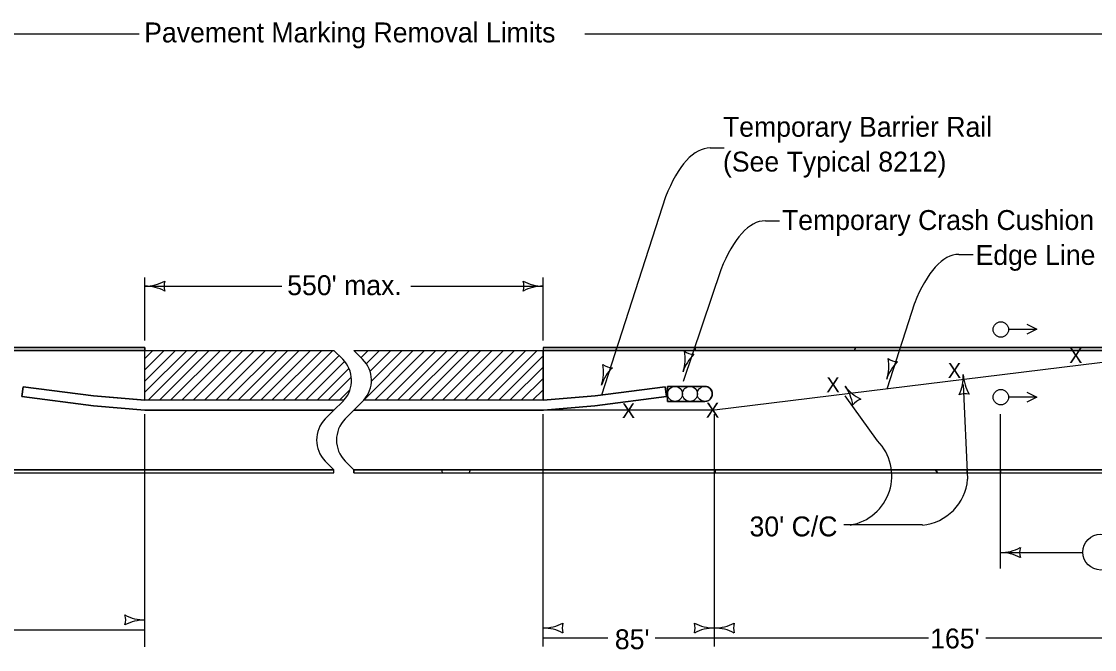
# Model space of a CAD drawing. Extents: x 10133 to 81668, y 4692 to 11018.
# Drawn here: x 22169 to 23247, y 6624 to 7255 of the extents above; entities that cross this region are included whole.
import ezdxf

# ---------------------------------------------------------------- set-up
doc = ezdxf.new("R2010")
doc.units = 0
for name, color, linetype in [('dsnCellElements', 7, 'Continuous'), ('dsnStdShading', 7, 'Continuous'), ('dsnTextTabulation', 7, 'Continuous'), ('Level 8', 7, 'Continuous')]:
    doc.layers.add(name, color=color, linetype=linetype)

msp = doc.modelspace()

# ---------------------------------------------------------------- linework, layer by layer
at = {"layer": 'dsnCellElements'}
for p, q in [((21627.5, 7243), (22286.9, 7243)), ((22734.5, 7243), (23352.5, 7243)), ((22860.4, 7128.3), (22874.6, 7128.3)), ((22815.7, 7079.2), (22751.3, 6880)), ((22915.9, 7055.2), (22930.1, 7055.2)), ((23110.4, 7021.4), (23124.6, 7021.4)), ((22292.5, 6934.8), (22292.5, 6998.1)), ((22692.5, 6934.8), (22692.5, 6998.1)), ((22871.1, 7006), (22833.2, 6893.5)), ((22292.5, 6989.5), (22430, 6989.5)), ((22559.8, 6989.5), (22692.5, 6989.5)), ((23065.7, 6972.2), (23037.8, 6886.1)), ((23160.3, 6946.3), (23188.2, 6946.3)), ((22292.5, 6924.8), (20982.5, 6924.8)), ((22292.5, 6916.7), (22300.6, 6924.8)), ((22292.5, 6905.4), (22311.9, 6924.8)), ((22292.5, 6894.1), (22323.2, 6924.8)), ((22292.5, 6874.8), (22292.5, 6924.8)), ((22292.5, 6882.8), (22334.5, 6924.8)), ((22292.5, 6874.8), (22292.5, 6924.8)), ((22295.8, 6874.8), (22345.8, 6924.8)), ((22307.1, 6874.8), (22357.1, 6924.8)), ((22318.4, 6874.8), (22368.4, 6924.8)), ((22329.7, 6874.8), (22379.7, 6924.8)), ((22341, 6874.8), (22391, 6924.8)), ((22352.3, 6874.8), (22402.3, 6924.8)), ((22413.7, 6924.8), (22363.7, 6874.8)), ((22375, 6874.8), (22425, 6924.8)), ((22386.3, 6874.8), (22436.3, 6924.8)), ((22397.6, 6874.8), (22447.6, 6924.8)), ((22408.9, 6874.8), (22458.9, 6924.8)), ((22420.2, 6874.8), (22470.2, 6924.8)), ((22431.5, 6874.8), (22481.5, 6924.8)), ((22491.3, 6916), (22482.5, 6924.8)), ((22511.3, 6916), (22502.5, 6924.8)), ((22509.8, 6917.6), (22517, 6924.8)), ((22513.7, 6876.3), (22562.2, 6924.8)), ((22515, 6911.5), (22528.3, 6924.8)), ((22518.7, 6903.9), (22539.6, 6924.8)), ((22520.1, 6894), (22550.9, 6924.8)), ((22523.5, 6874.8), (22573.5, 6924.8)), ((22534.8, 6874.8), (22584.8, 6924.8)), ((22546.2, 6874.8), (22596.2, 6924.8)), ((22557.5, 6874.8), (22607.5, 6924.8)), ((22568.8, 6874.8), (22618.8, 6924.8)), ((22580.1, 6874.8), (22630.1, 6924.8)), ((22591.4, 6874.8), (22641.4, 6924.8)), ((22602.7, 6874.8), (22652.7, 6924.8)), ((22614, 6874.8), (22664, 6924.8)), ((22625.4, 6874.8), (22675.4, 6924.8)), ((22636.7, 6874.8), (22686.7, 6924.8)), ((22692.5, 6874.8), (22692.5, 6924.8)), ((24005, 6924.8), (22692.5, 6924.8)), ((22692.5, 6924.8), (22692.5, 6874.8)), ((23352.5, 6924.8), (22864.7, 6864.8)), ((22442.9, 6874.8), (22487.7, 6919.6)), ((22454.2, 6874.8), (22493.2, 6913.9)), ((22648, 6874.8), (22692.5, 6919.3)), ((22465.5, 6874.8), (22497.6, 6906.9)), ((22659.3, 6874.8), (22692.5, 6908)), ((22476.8, 6874.8), (22499.9, 6897.9)), ((22670.6, 6874.8), (22692.5, 6896.7)), ((23114.7, 6890.6), (23119.1, 6795.4)), ((22170.3, 6888.3), (22169, 6878.4)), ((22170.3, 6888.3), (22169, 6878.4)), ((22169, 6878.4), (22170.3, 6888.3)), ((22169, 6878.4), (22170.3, 6888.3)), ((22169, 6878.5), (22241, 6869.1)), ((22169, 6878.4), (22241, 6869.1)), ((22241, 6869.1), (22169, 6878.4)), ((22241, 6869.1), (22169, 6878.4)), ((22240.8, 6879.1), (22170.3, 6888.3)), ((22240.8, 6879.1), (22170.3, 6888.3)), ((22240.8, 6879.1), (22170.3, 6888.3)), ((22170.3, 6888.3), (22240.8, 6879.1)), ((22292.9, 6874.8), (22240.8, 6879.1)), ((22292.5, 6874.8), (22240.8, 6879.1)), ((22292.5, 6874.8), (22240.8, 6879.1)), ((22240.8, 6879.1), (22292.5, 6874.8)), ((22488.1, 6874.8), (22498.5, 6885.2)), ((22681.9, 6874.8), (22692.5, 6885.4)), ((22692.5, 6874.8), (22744.8, 6879.1)), ((22744.8, 6879.1), (22692.7, 6874.8)), ((22692.7, 6874.8), (22744.8, 6879.1)), ((22744.6, 6869.1), (22816.6, 6878.5)), ((22816.6, 6878.5), (22744.6, 6869.1)), ((22816.6, 6878.5), (22744.6, 6869.1)), ((22815.3, 6888.3), (22744.8, 6879.1)), ((22744.8, 6879.1), (22815.3, 6888.3)), ((22744.8, 6879.1), (22815.3, 6888.3)), ((22816.6, 6878.5), (22815.3, 6888.3)), ((22815.3, 6888.3), (22816.6, 6878.5)), ((22815.3, 6888.3), (22816.6, 6878.5)), ((22817.6, 6888.7), (22817.6, 6873.7)), ((22855.1, 6888.7), (22817.6, 6888.7)), ((22817.6, 6873.7), (22817.6, 6888.7)), ((22817.6, 6888.7), (22855.1, 6888.7)), ((23028.6, 6833.9), (22996, 6879.1)), ((22241, 6869.1), (22292.5, 6864.8)), ((22241, 6869.1), (22292.5, 6864.8)), ((22292.5, 6864.8), (22241, 6869.1)), ((22292.5, 6864.8), (22241, 6869.1)), ((22292.8, 6874.8), (22292.5, 6874.8)), ((22292.5, 6874.8), (22292.5, 6874.8)), ((22492.5, 6874.8), (22292.5, 6874.8)), ((22292.9, 6874.8), (22292.8, 6874.8)), ((22492.5, 6874.8), (22292.9, 6874.8)), ((22482.5, 6864.8), (22491.3, 6873.6)), ((22482.5, 6864.8), (22491.3, 6873.6)), ((22511.3, 6873.6), (22502.5, 6864.8)), ((22502.5, 6864.8), (22511.3, 6873.6)), ((22692.7, 6874.8), (22512.5, 6874.8)), ((22692.7, 6874.8), (22512.5, 6874.8)), ((22693.1, 6864.8), (22744.6, 6869.1)), ((22744.6, 6869.1), (22693.1, 6864.8)), ((22744.6, 6869.1), (22693.1, 6864.8)), ((22817.6, 6873.7), (22855.1, 6873.7)), ((22855.1, 6873.7), (22817.6, 6873.7)), ((23160.3, 6878.2), (23188.2, 6878.2)), ((22292.5, 6864.8), (22482.5, 6864.8)), ((22292.5, 6864.8), (22482.5, 6864.8)), ((22482.5, 6864.8), (22292.5, 6864.8)), ((22482.5, 6864.8), (22292.5, 6864.8)), ((22292.5, 6626.9), (22292.5, 6860.7)), ((22473.7, 6856), (22482.5, 6864.8)), ((22473.7, 6856), (22482.5, 6864.8)), ((22493.7, 6856), (22502.5, 6864.8)), ((22502.5, 6864.8), (22693.1, 6864.8)), ((22693.1, 6864.8), (22502.5, 6864.8)), ((22693.1, 6864.8), (22502.5, 6864.8)), ((22692.5, 6627.2), (22692.5, 6860.7)), ((22864.7, 6864.8), (22693.1, 6864.8)), ((22864.7, 6627.2), (22864.7, 6860.7)), ((23152, 6705.8), (23152, 6860.7)), ((20982.5, 6804.8), (22482.5, 6804.8)), ((22482.5, 6804.8), (22473.7, 6813.6)), ((22482.5, 6804.8), (22473.7, 6813.6)), ((22482.5, 6801.8), (22482.5, 6804.8)), ((22493.7, 6813.6), (22502.5, 6804.8)), ((22502.5, 6804.8), (22493.7, 6813.6)), ((22502.5, 6801.8), (22502.5, 6804.8)), ((22502.5, 6804.8), (24005, 6804.8)), ((23073.8, 6749.5), (22994.7, 6749.5)), ((23152, 6721.7), (23234.9, 6721.7)), ((21991.3, 6644), (22292.5, 6644)), ((22692.5, 6635.9), (22757.5, 6635.9)), ((22805.1, 6635.9), (22864.7, 6635.9)), ((22864.7, 6635.9), (23079.7, 6635.9)), ((23137.5, 6635.9), (23352.5, 6635.9))]:
    msp.add_line(p, q, dxfattribs=at)
for points in [[(23178.6, 6951.1), (23188.6, 6946.1), (23178.6, 6941.1)], [(22292.5, 6924.8), (22482.5, 6924.8)], [(22502.5, 6924.8), (22692.5, 6924.8)], [(23178.6, 6883), (23188.6, 6878), (23178.6, 6873)], [(22292.9, 6874.8), (22292.9, 6874.8)], [(22512.5, 6874.8), (22512.5, 6874.8)], [(22482.5, 6864.8), (22482.5, 6864.8)], [(22482.5, 6864.8), (22482.5, 6864.8)], [(22502.5, 6864.8), (22502.5, 6864.8), (22493.7, 6856)]]:
    msp.add_lwpolyline(points, dxfattribs=at)
for centre, radius in [((23152.5, 6945.9), 7.74), ((22825.1, 6881.2), 7.5), ((22825.1, 6881.2), 7.5), ((22840.1, 6881.2), 7.5), ((22840.1, 6881.2), 7.5), ((22855.1, 6881.2), 7.5), ((22855.1, 6881.2), 7.5), ((23152.5, 6877.9), 7.74), ((23252.9, 6722.2), 18)]:
    msp.add_circle(centre, radius, dxfattribs=at)
for centre, radius, start, end in [((22292.5, 7032), 42.5, 270, 298.0725), ((22292.5, 6947), 42.5, 61.9275, 90), ((22328.2, 6989.5), 16.4, 162.2666, 197.7334), ((22656.9, 6989.5), 16.4, 342.2666, 17.7333), ((22692.5, 7032), 42.5, 241.9275, 270), ((22692.5, 6947), 42.5, 90, 118.0725), ((22470.1, 6894.8), 30, 318.1884, 45), ((22490.1, 6894.8), 30, 318.1884, 45), ((22855.1, 6881.2), 7.5, 269.9996, 90), ((22470.1, 6894.8), 30, 315, 318.1884), ((22470.1, 6894.8), 30, 315.0008, 318.1884), ((22490.1, 6894.8), 30, 315, 318.2713), ((22490.1, 6894.8), 30, 315.0008, 318.1884), ((22495, 6834.8), 30, 135, 225), ((22495, 6834.8), 30, 135, 225), ((22515, 6834.8), 30, 135, 225), ((22515, 6834.8), 30, 135, 225), ((22992.9, 6798.8), 50.1, 279.6171, 44.516), ((23069.2, 6799.3), 50.1, 275.2646, 355.5485), ((23152, 6764.2), 42.5, 270, 298.0725), ((23152, 6679.2), 42.5, 61.9275, 90), ((23187.7, 6721.7), 16.4, 162.2666, 197.7334)]:
    msp.add_arc(centre, radius, start, end, dxfattribs=at)
for centre in [(22860.4, 6915.4), (22915.9, 6842.2), (23110.4, 6808.4)]:
    msp.add_ellipse(centre, major_axis=(0, 212.9), ratio=0.328743, start_param=0, end_param=0.693162, dxfattribs=at)
at = {"layer": 'dsnStdShading'}
for p, q in [((22855.1, 6888.7), (22817.6, 6888.7)), ((22817.6, 6888.7), (22817.6, 6873.7)), ((22817.6, 6873.7), (22855.1, 6873.7))]:
    msp.add_line(p, q, dxfattribs=at)
msp.add_arc((22855.1, 6881.2), 7.5, 270.0024, 89.9972, dxfattribs=at)
at = {"layer": 'dsnTextTabulation'}
for p, q in [((22292.5, 6927.8), (22100.5, 6927.8)), ((22292.5, 6924.8), (22292.5, 6927.8)), ((22292.5, 6927.8), (22292.5, 6924.8)), ((22692.5, 6927.8), (22692.5, 6924.8)), ((22692.5, 6927.8), (22692.5, 6924.8)), ((22766.7, 6927.8), (22692.5, 6927.8)), ((22692.5, 6924.8), (22693.2, 6924.8)), ((22693.2, 6924.8), (22765.8, 6924.8)), ((22766.7, 6927.8), (22765.8, 6924.8)), ((22765.8, 6924.8), (22766.7, 6927.8)), ((22765.8, 6924.8), (22844.9, 6924.8)), ((22845.8, 6927.8), (22766.7, 6927.8)), ((22845.8, 6927.8), (22844.9, 6924.8)), ((22844.9, 6924.8), (22845.8, 6927.8)), ((22844.9, 6924.8), (23005.3, 6924.8)), ((23006.3, 6927.8), (22845.8, 6927.8)), ((23006.3, 6927.8), (23005.3, 6924.8)), ((23005.3, 6924.8), (23006.3, 6927.8)), ((23005.3, 6924.8), (23298.3, 6924.8)), ((23320, 6927.8), (23006.3, 6927.8)), ((20982.5, 6804.8), (22482.5, 6804.8)), ((20982.5, 6804.8), (22482.5, 6804.8)), ((22482.5, 6804.8), (21632.5, 6804.8)), ((22482.5, 6801.8), (22482.5, 6804.8)), ((22502.5, 6804.8), (24005, 6804.8)), ((22502.5, 6804.8), (24005, 6804.8)), ((22590.6, 6804.8), (22502.5, 6804.8)), ((22502.5, 6804.8), (22502.5, 6801.8)), ((22619.4, 6804.8), (22590.6, 6804.8)), ((22865.5, 6804.8), (22619.4, 6804.8)), ((22865.5, 6801.8), (22865.5, 6804.8)), ((23086.8, 6804.8), (22865.5, 6804.8)), ((22865.5, 6804.8), (22865.5, 6801.8)), ((23089, 6801.8), (23086.8, 6804.8)), ((23086.8, 6804.8), (23089, 6801.8)), ((23118.6, 6804.8), (23086.8, 6804.8)), ((23118.8, 6801.8), (23118.6, 6804.8)), ((23152, 6804.8), (23118.6, 6804.8)), ((23118.6, 6804.8), (23118.8, 6801.8)), ((23152, 6801.8), (23152, 6804.8)), ((23425.9, 6804.8), (23152, 6804.8)), ((23152, 6804.8), (23152, 6801.8)), ((20982.5, 6801.8), (22482.5, 6801.8)), ((20982.5, 6801.8), (22482.5, 6801.8)), ((22502.5, 6801.8), (24005, 6801.8)), ((22502.5, 6801.8), (22591.6, 6801.8)), ((22591.6, 6801.8), (22618.5, 6801.8)), ((22618.5, 6801.8), (22865.5, 6801.8)), ((22865.5, 6801.8), (23089, 6801.8)), ((23089, 6801.8), (23118.8, 6801.8)), ((23118.8, 6801.8), (23152, 6801.8)), ((23152, 6801.8), (23424.9, 6801.8))]:
    msp.add_line(p, q, dxfattribs=at)
for points in [[(20982.5, 6927.8), (22292.5, 6927.8)], [(20982.5, 6924.8), (22292.5, 6924.8)], [(22102.7, 6924.8), (22292.1, 6924.8), (22292.5, 6924.8)], [(22692.5, 6927.8), (24005, 6927.8)], [(22692.5, 6924.8), (24005, 6924.8)]]:
    msp.add_lwpolyline(points, dxfattribs=at)
for start, end in [(191.3299, 203.618), (191.3299, 203.618), (336.382, 348.6701), (336.382, 348.6701)]:
    msp.add_arc((22605, 6807.7), 14.7, start, end, dxfattribs=at)
at = {"layer": 'Level 8'}
for centre, radius, start, end in [((22792.8, 6916.6), 42.5, 342.0849, 10.1574), ((22844.2, 6937.4), 16.4, 234.3516, 269.8183), ((22873.6, 6890.4), 42.5, 134.0124, 162.0849), ((22997.4, 6909.2), 42.5, 342.0849, 10.1574), ((23078.3, 6883), 42.5, 134.0124, 162.0849), ((23048.8, 6930), 16.4, 234.3516, 269.8183), ((22710.8, 6903.1), 42.5, 342.0849, 10.1574), ((22791.7, 6876.9), 42.5, 134.0124, 162.0849), ((22762.2, 6923.9), 16.4, 234.3516, 269.8183), ((23072.3, 6898.6), 42.5, 334.5429, 2.6154), ((23157.2, 6902.5), 42.5, 182.6154, 210.6879), ((23030.2, 6914.2), 42.5, 216.299, 244.3715), ((22961.7, 6863.9), 42.5, 8.2265, 36.299), ((23116.3, 6865), 16.4, 74.8821, 110.3488), ((23017.1, 6860.4), 16.4, 108.5657, 144.0324), ((22256.9, 6654), 16.4, 342.2666, 17.7333), ((22292.5, 6696.5), 42.5, 241.9275, 270), ((22292.5, 6611.5), 42.5, 90, 118.0725), ((22692.5, 6688.4), 42.5, 270, 298.0725), ((22692.5, 6603.4), 42.5, 61.9275, 90), ((22728.2, 6645.9), 16.4, 162.2666, 197.7334), ((22829, 6645.9), 16.4, 342.2666, 17.7333), ((22864.7, 6688.4), 42.5, 241.9275, 270), ((22864.7, 6603.4), 42.5, 90, 118.0725), ((22864.7, 6688.4), 42.5, 270, 298.0725), ((22864.7, 6603.4), 42.5, 61.9275, 90), ((22900.3, 6645.9), 16.4, 162.2666, 197.7334)]:
    msp.add_arc(centre, radius, start, end, dxfattribs=at)

# ---------------------------------------------------------------- texts
at = {"layer": 'dsnCellElements'}
for s, height, p in [('Pavement Marking Removal Limits', 20, (22291.8, 7234.4)), ('Temporary Barrier Rail', 20, (22873.3, 7139.6)), ('(See Typical 8212)', 20, (22873.3, 7104.6)), ('Temporary Crash Cushion', 20, (22932.6, 7045.9)), ('Edge Line', 20, (23127.1, 7010.8)), ("550' max.", 20, (22435.5, 6980.4)), ('X', 15, (23221.1, 6912.1)), ('X', 15, (23099.2, 6897.2)), ('X', 15, (22977.2, 6882.9)), ('X', 15, (22771.7, 6856.8)), ('X', 15, (22856.2, 6857.4)), ("30' C/C", 20, (22900, 6738)), ("85'", 20, (22764.7, 6624.6)), ("165'", 20, (23081.5, 6625.4))]:
    msp.add_text(s, height=height, dxfattribs=at).set_placement(p)

doc.saveas('drawing.dxf')
